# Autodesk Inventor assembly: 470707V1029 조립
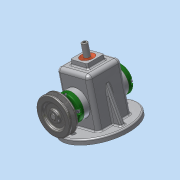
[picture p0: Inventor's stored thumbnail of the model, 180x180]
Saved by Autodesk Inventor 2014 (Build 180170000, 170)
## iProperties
Created: 2017-07
Part Number: 470707V1029 조립
Document SubType Name: Weldment
Designer: 406-9
Weld Material: Welded Aluminum-6061
Author: 406-9
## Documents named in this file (16)
- C:\Users\406-9\Desktop\470707V1029\470707V1029 조립.iam
- C:\Users\406-9\Desktop\470707V1029\470707V1029 본체.ipt
- C:\Users\406-9\Desktop\470707V1029\V벨트풀리.ipt
- C:\Users\406-9\Desktop\470707V1029\고정핀 1.2 x  8.ipt
- C:\Users\406-9\Desktop\470707V1029\뒤커버.ipt
- C:\Users\406-9\Desktop\470707V1029\링크.ipt
- C:\Users\406-9\Desktop\470707V1029\멈춤나사 M3x8.ipt
- C:\Users\406-9\Desktop\470707V1029\베어링 12 x 32 x 10.ipt
- C:\Users\406-9\Desktop\470707V1029\볼트 M4 x 12.ipt
- C:\Users\406-9\Desktop\470707V1029\부시.ipt
- C:\Users\406-9\Desktop\470707V1029\슬라이드.ipt
- C:\Users\406-9\Desktop\470707V1029\앞커버.ipt
- C:\Users\406-9\Desktop\470707V1029\오일실 12 25 7.ipt
- C:\Users\406-9\Desktop\470707V1029\키 4 x 4 x 10.ipt
- C:\Users\406-9\Desktop\470707V1029\편심축.ipt
- C:\Users\406-9\Desktop\470707V1029\핀 5 x 18.ipt
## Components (4 placed, 4 different names)
1. 470707V1029 본체:2
2. V벨트풀리:2 — 플러쉬:1
3. 핀 5 x 18:2
4. 고정핀 1.2 x  8:3
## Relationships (1: Flush 1)
- 플러쉬:1 [Flush]: V벨트풀리:2
